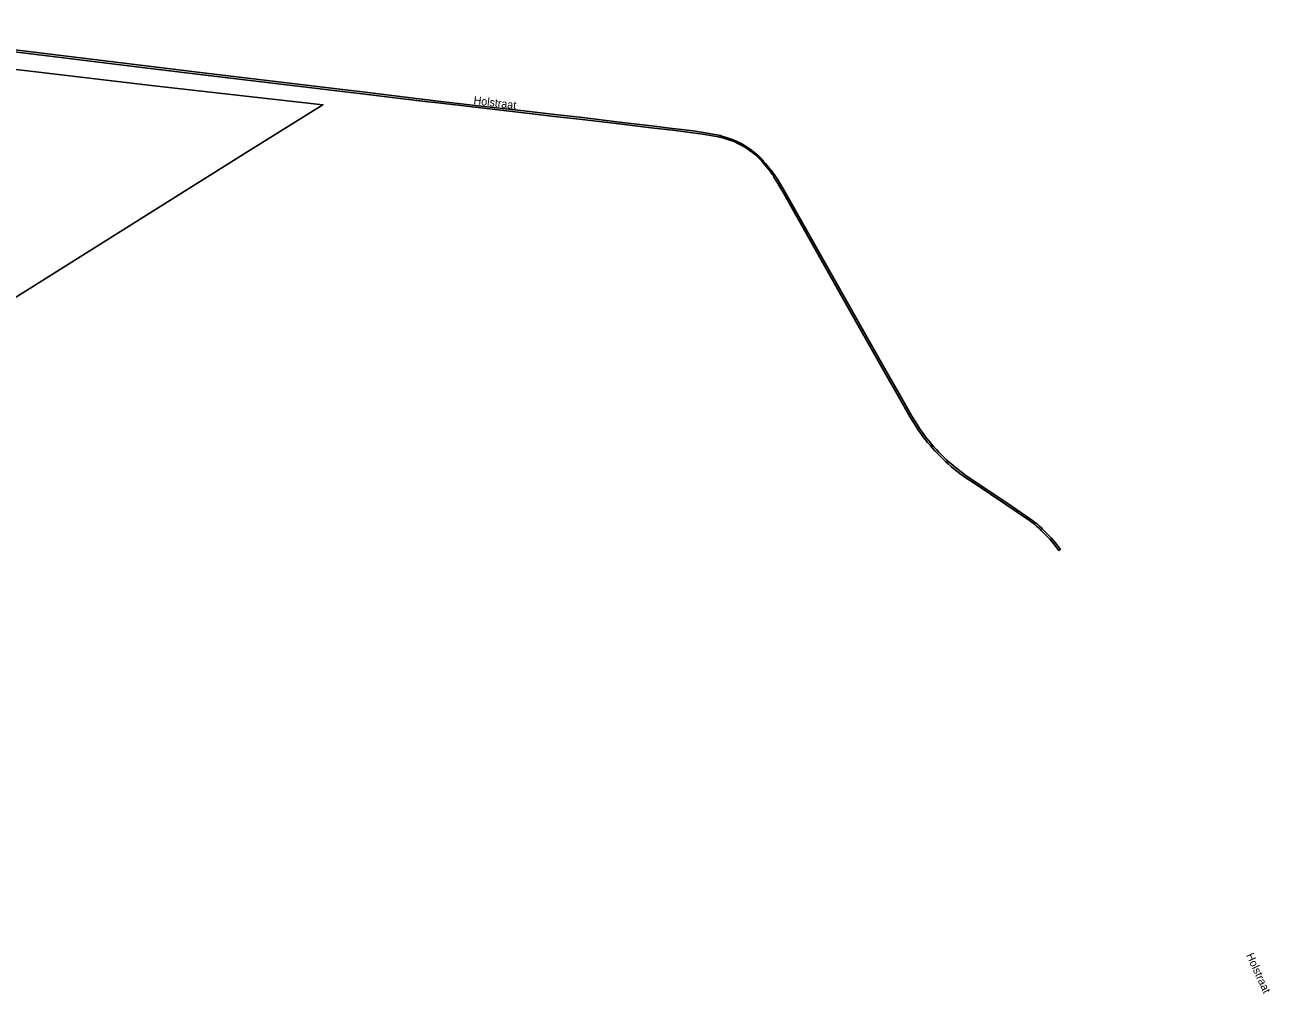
# Model space of a CAD drawing. Extents: x 141000 to 143000, y 400580 to 403500.
# Drawn here: x 141534.2 to 141923.2, y 401317 to 401619.8 of the extents above; entities that cross this region are included whole.
import ezdxf

# ---------------------------------------------------------------- set-up
doc = ezdxf.new("R2010")
doc.units = 0
doc.layers.add('gg-anno-openbare ruimte label', color=7, linetype='Continuous')
doc.layers.add('gx-grn-maaiveld', color=7, linetype='Continuous')

msp = doc.modelspace()

# ---------------------------------------------------------------- linework, layer by layer
at = {"layer": 'gx-grn-maaiveld'}
for points in [[(141466.46, 401619.77), (141530.27, 401612.04), (141590.76, 401604.66), (141633.49, 401599.59), (141639.68, 401598.84), (141662.45, 401596.1), (141675.01, 401594.64), (141690.11, 401592.93), (141699.77, 401591.8), (141708.4, 401590.8), (141720, 401589.43), (141729.98, 401588.23), (141736.57, 401587.43), (141742.95, 401586.64), (141746.15, 401586.2), (141751, 401585.36), (141751.62, 401585.22), (141751.59, 401585.07), (141751.99, 401584.98)], [(141524.15, 401612.18), (141530.2, 401611.45), (141572.54, 401606.28), (141590.68, 401604.06), (141633.41, 401599), (141639.6, 401598.24), (141660.07, 401595.78), (141662.38, 401595.51), (141674.94, 401594.05), (141690.05, 401592.33), (141699.7, 401591.2), (141708.33, 401590.2), (141719.93, 401588.84), (141729.91, 401587.64), (141736.5, 401586.84), (141742.87, 401586.04), (141746.06, 401585.61)], [(141531.54, 401605.86), (141574.58, 401600.74), (141627.33, 401594.83), (141604.73, 401580.77), (141526.2, 401531.45)], [(141750.9, 401584.77), (141751.49, 401584.64), (141751.5, 401584.68), (141751.9, 401584.59)], [(141767.41, 401573.58), (141768.25, 401572.41), (141768.12, 401572.31), (141768.82, 401571.31), (141771.29, 401567.06), (141790.08, 401533.77), (141802.62, 401511.53), (141807.13, 401503.67), (141810.82, 401497.23), (141812.42, 401494.63), (141813.41, 401493.09)], [(141813.92, 401493.41), (141812.93, 401494.94), (141811.34, 401497.53), (141807.65, 401503.97), (141803.14, 401511.82), (141790.6, 401534.07), (141771.81, 401567.36), (141769.34, 401571.61), (141768.57, 401572.64), (141767.73, 401573.82)], [(141826.3, 401479.67), (141827.87, 401478.55), (141830.78, 401476.59), (141841, 401469.77), (141848.07, 401464.94)], [(141848.4, 401465.43), (141841.33, 401470.27), (141831.11, 401477.09), (141828.2, 401479.04), (141826.67, 401480.14)], [(141852.24, 401461.36), (141853.67, 401459.87), (141854.39, 401459.17), (141855.03, 401458.42), (141855.69, 401457.63), (141857.15, 401455.73), (141857.26, 401455.59), (141857.67, 401455.9), (141857.73, 401455.95), (141856.17, 401458), (141854.81, 401459.6), (141852.66, 401461.78)]]:
    msp.add_lwpolyline(points, dxfattribs=at)
for centre, radius, start, end in [((141688.44, 401238.6), 351.76, 79.7733, 80.5721), ((141745.76, 401559.79), 25.55, 51.7741, 76.0955), ((141745.75, 401559.76), 25.98, 46.8586, 76.081), ((141745.58, 401559.58), 25.83, 46.8734, 51.7545), ((141726.26, 401542.43), 51.6, 37.1229, 44.2312), ((141728.82, 401544.87), 48.47, 43.1397, 44.2995), ((141726.48, 401542.6), 51.73, 37.1173, 43.1971), ((141862.93, 401527.75), 60.45, 214.9942, 232.7022), ((141862.91, 401527.73), 59.82, 215.0094, 232.7051), ((141828.54, 401438.01), 33.26, 44.5746, 54.0555), ((141828.64, 401438.12), 33.71, 44.5591, 54.1099)]:
    msp.add_arc(centre, radius, start, end, dxfattribs=at)

# ---------------------------------------------------------------- texts
at = {"layer": 'gg-anno-openbare ruimte label'}
for rotation, p in [(352.9, (141674.29, 401595.07)), (294.5, (141915.68, 401329.18))]:
    msp.add_text('Holstraat', height=2.5, rotation=rotation, dxfattribs=at).set_placement(p)

doc.saveas('drawing.dxf')
